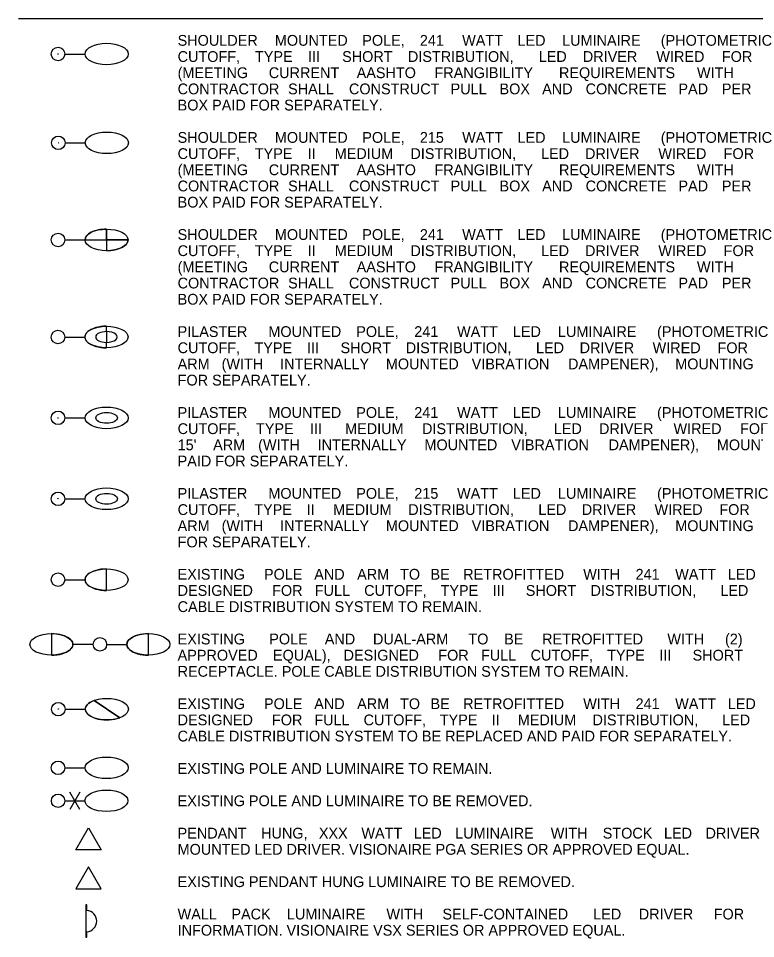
# Model space of a CAD drawing. Extents: x -1452 to -654, y -278 to 245.
# Drawn here: x -1424.2 to -1219, y -15.4 to 240.5 of the extents above; entities that cross this region are included whole.
import ezdxf

# ---------------------------------------------------------------- set-up
doc = ezdxf.new("R2010")
doc.units = 0
for name, color, linetype in [('AdhocPoint_dp', 7, 'Continuous'), ('Logo_dp', 7, 'Continuous'), ('Miscellaneous3', 7, 'Continuous'), ('SheetBorder_dp', 7, 'Continuous'), ('SheetLines_dp', 7, 'Continuous'), ('TextMisc', 7, 'Continuous')]:
    doc.layers.add(name, color=color, linetype=linetype)

# ---------------------------------------------------------------- blocks, each defined once
blk = doc.blocks.new('EPoleLumRmv')
at = {"layer": 'Logo_dp'}
for p, q in [((0, -0.00271), (0, -0.01083)), ((-0.00352, -0.0088), (0.00352, -0.00474)), ((0.00352, -0.0088), (-0.00352, -0.00474))]:
    blk.add_line(p, q, dxfattribs=at)
blk.add_circle((0, 0), 0.00271, dxfattribs=at)
blk.add_ellipse((0, -0.01949), major_axis=(0, -0.00866), ratio=0.5, dxfattribs=at)

msp = doc.modelspace()

# ---------------------------------------------------------------- linework, layer by layer
at = {"layer": 'AdhocPoint_dp'}
for p, q in [((-1405.09, -6.02), (-1405.39, -6.02)), ((-1405.39, -6.02), (-1405.39, -15.02)), ((-1405.09, -7.54), (-1405.09, -6.02)), ((-1405.39, -15.02), (-1405.09, -15.02)), ((-1405.09, -15.02), (-1405.09, -13.51))]:
    msp.add_line(p, q, dxfattribs=at)
for points in [[(-1401.1, 9.31), (-1408.17, 9.31), (-1404.64, 15.43)], [(-1408.17, -1.53), (-1401.1, -1.53), (-1404.64, 4.59)]]:
    msp.add_lwpolyline(points, close=True, dxfattribs=at)
msp.add_arc((-1405.39, -10.52), 3, 275.7392, 84.2608, dxfattribs=at)
at = {"layer": 'Logo_dp'}
msp.add_line((-1411.26, 32.11), (-1405.63, 32.11), dxfattribs=at)
msp.add_circle((-1413.13, 32.11), 1.88, dxfattribs=at)
msp.add_ellipse((-1399.63, 32.11), major_axis=(6, 0), ratio=0.5, dxfattribs=at)
at = {"layer": 'Miscellaneous3'}
msp.add_line((-1424.17, 240.54), (-654.17, 240.54), dxfattribs=at)
at = {"layer": 'SheetLines_dp'}
for p, q in [((-1413.16, 230.6), (-1413.16, 230.67)), ((-1413.16, 230.67), (-1413.09, 230.67)), ((-1413.09, 230.6), (-1413.16, 230.67)), ((-1413.09, 230.6), (-1413.16, 230.6)), ((-1413.09, 230.67), (-1413.09, 230.6)), ((-1413.08, 205.89), (-1413.08, 205.97)), ((-1413.08, 205.97), (-1413.01, 205.97)), ((-1413.01, 205.89), (-1413.08, 205.97)), ((-1413.01, 205.89), (-1413.08, 205.89)), ((-1413.01, 205.97), (-1413.01, 205.89)), ((-1413.16, 129.39), (-1413.16, 129.47)), ((-1413.16, 129.47), (-1413.09, 129.47)), ((-1413.09, 129.39), (-1413.16, 129.47)), ((-1413.09, 129.39), (-1413.16, 129.39)), ((-1413.09, 129.47), (-1413.09, 129.39)), ((-1413.16, 106.89), (-1413.16, 106.97)), ((-1413.16, 106.97), (-1413.09, 106.97)), ((-1413.09, 106.89), (-1413.16, 106.97)), ((-1413.09, 106.89), (-1413.16, 106.89)), ((-1413.09, 106.97), (-1413.09, 106.89)), ((-1413.08, 48.39), (-1413.08, 48.47)), ((-1413.08, 48.47), (-1413.01, 48.47)), ((-1413.01, 48.39), (-1413.08, 48.47)), ((-1413.01, 48.39), (-1413.08, 48.39)), ((-1413.01, 48.47), (-1413.01, 48.39))]:
    msp.add_line(p, q, dxfattribs=at)
at = {"layer": 'TextMisc'}
for p, q in [((-1411.25, 230.63), (-1405.63, 230.63)), ((-1411.17, 205.93), (-1405.55, 205.93)), ((-1399.64, 181.93), (-1399.64, 175.93)), ((-1399.64, 178.93), (-1399.64, 181.93)), ((-1411.25, 178.93), (-1405.63, 178.93)), ((-1405.63, 178.93), (-1393.65, 178.93)), ((-1405.63, 178.93), (-1399.64, 178.93)), ((-1393.65, 178.93), (-1399.64, 178.93)), ((-1399.64, 178.93), (-1399.64, 175.93)), ((-1399.67, 153.43), (-1399.67, 154.93)), ((-1411.29, 151.91), (-1405.66, 151.92)), ((-1399.67, 153.43), (-1399.66, 150.43)), ((-1399.66, 148.93), (-1399.66, 150.43)), ((-1411.25, 129.43), (-1405.63, 129.43)), ((-1411.25, 106.93), (-1405.63, 106.93)), ((-1399.64, 81.43), (-1399.64, 87.43)), ((-1411.25, 84.43), (-1405.63, 84.43)), ((-1414.98, 69.43), (-1414.98, 63.43)), ((-1388.01, 63.43), (-1388.01, 69.43)), ((-1403.37, 66.43), (-1408.99, 66.43)), ((-1399.62, 66.43), (-1394, 66.43)), ((-1403.11, 50.84), (-1395.98, 46.02)), ((-1395.98, 46.02), (-1403.11, 50.84)), ((-1411.17, 48.43), (-1405.55, 48.43))]:
    msp.add_line(p, q, dxfattribs=at)
for centre in [(-1413.13, 230.63), (-1413.05, 205.93), (-1413.13, 178.93), (-1413.16, 151.91), (-1413.13, 129.43), (-1413.13, 106.93), (-1413.13, 84.43), (-1401.49, 66.43), (-1401.49, 66.43), (-1413.05, 48.43)]:
    msp.add_circle(centre, 1.88, dxfattribs=at)
for centre, major_axis in [((-1399.63, 230.63), (6, 0)), ((-1399.55, 205.93), (6, 0)), ((-1399.64, 178.93), (5.99, 0)), ((-1399.66, 151.93), (6, 0.01)), ((-1399.63, 129.43), (6, 0)), ((-1399.63, 129.43), (3, 0)), ((-1399.63, 106.93), (6, 0)), ((-1399.63, 106.93), (3, 0)), ((-1399.63, 106.93), (3, 0)), ((-1399.64, 84.43), (5.99, 0)), ((-1414.98, 66.43), (-5.99, 0)), ((-1388.01, 66.43), (5.99, 0)), ((-1399.55, 48.43), (6, 0))]:
    msp.add_ellipse(centre, major_axis=major_axis, ratio=0.5, dxfattribs=at)
for centre, major_axis, start_param, end_param in [((-1399.64, 178.93), (5.99, 0), 1.570796, 3.141593), ((-1399.64, 178.93), (5.99, 0), 4.712389, 6.283185), ((-1399.66, 151.93), (6, 0.01), 1.570796, 4.712389), ((-1399.66, 151.93), (3, 0), 1.570796, 3.141593), ((-1399.66, 151.93), (3, 0), 3.141593, 4.712389), ((-1399.66, 151.93), (3, 0), 4.712389, 7.853982), ((-1399.64, 84.43), (5.99, 0), 1.570796, 4.712389), ((-1414.98, 66.43), (-5.99, 0), 1.570796, 4.712389), ((-1388.01, 66.43), (5.99, 0), 1.570796, 4.712389), ((-1399.55, 48.43), (6, 0), 2.207405, 5.348998)]:
    msp.add_ellipse(centre, major_axis=major_axis, ratio=0.5, start_param=start_param, end_param=end_param, dxfattribs=at)

# ---------------------------------------------------------------- block references
at = {"layer": 'Logo_dp', "xscale": 690.9505022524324, "yscale": 690.9505022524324, "rotation": 89.99999999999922}
msp.add_blockref('EPoleLumRmv', (-1413.13, 22.94), dxfattribs=at)

# ---------------------------------------------------------------- texts
at = {"layer": 'SheetBorder_dp'}
for s, p in [('SHOULDER ', (-1379.86, 232.93)), ('MOUNTED ', (-1352.8, 232.93)), ('POLE, ', (-1328.47, 232.93)), ('241 ', (-1312.46, 232.93)), ('WATT ', (-1300.68, 232.93)), ('LED ', (-1285.28, 232.93)), ('LUMINAIRE ', (-1272.86, 232.93)), ('(PHOTOMETRIC ', (-1245.41, 232.93)), ('CUTOFF, ', (-1379.86, 228.43)), ('TYPE ', (-1358.33, 228.43)), ('III ', (-1343.56, 228.43)), ('SHORT ', (-1334.09, 228.43)), ('DISTRIBUTION, ', (-1315.78, 228.43)), ('LED ', (-1279.39, 228.43)), ('DRIVER ', (-1267.1, 228.43)), ('WIRED ', (-1246.64, 228.43)), ('FOR ', (-1228.41, 228.43)), ('(MEETING ', (-1379.86, 223.93)), ('CURRENT ', (-1354.5, 223.93)), ('AASHTO ', (-1330.04, 223.93)), ('FRANGIBILITY ', (-1308.39, 223.93)), ('REQUIREMENTS ', (-1273.74, 223.93)), ('WITH ', (-1235.34, 223.93)), ('CONTRACTOR ', (-1379.86, 219.43)), ('SHALL ', (-1349.13, 219.43)), ('CONSTRUCT ', (-1332.18, 219.43)), ('PULL ', (-1303.9, 219.43)), ('BOX ', (-1290.29, 219.43)), ('AND ', (-1278.42, 219.43)), ('CONCRETE ', (-1266.32, 219.43)), ('PAD ', (-1240.5, 219.43)), ('PER ', (-1228.42, 219.43)), ('BOX PAID FOR SEPARATELY.', (-1379.86, 214.93)), ('SHOULDER ', (-1379.86, 205.93)), ('MOUNTED ', (-1352.8, 205.93)), ('POLE, ', (-1328.47, 205.93)), ('215 ', (-1312.46, 205.93)), ('WATT ', (-1300.68, 205.93)), ('LED ', (-1285.28, 205.93)), ('LUMINAIRE ', (-1272.86, 205.93)), ('(PHOTOMETRIC ', (-1245.41, 205.93)), ('CUTOFF, ', (-1379.86, 201.43)), ('TYPE ', (-1358.39, 201.43)), ('II ', (-1343.67, 201.43)), ('MEDIUM ', (-1336.14, 201.43)), ('DISTRIBUTION, ', (-1315.08, 201.43)), ('LED ', (-1278.74, 201.43)), ('DRIVER ', (-1266.5, 201.43)), ('WIRED ', (-1246.09, 201.43)), ('FOR ', (-1227.92, 201.43)), ('(MEETING ', (-1379.86, 196.93)), ('CURRENT ', (-1354.5, 196.93)), ('AASHTO ', (-1330.04, 196.93)), ('FRANGIBILITY ', (-1308.39, 196.93)), ('REQUIREMENTS ', (-1273.74, 196.93)), ('WITH ', (-1235.34, 196.93)), ('CONTRACTOR ', (-1379.86, 192.43)), ('SHALL ', (-1349.13, 192.43)), ('CONSTRUCT ', (-1332.18, 192.43)), ('PULL ', (-1303.9, 192.43)), ('BOX ', (-1290.29, 192.43)), ('AND ', (-1278.42, 192.43)), ('CONCRETE ', (-1266.32, 192.43)), ('PAD ', (-1240.5, 192.43)), ('PER ', (-1228.42, 192.43)), ('BOX PAID FOR SEPARATELY.', (-1379.86, 187.93)), ('SHOULDER ', (-1379.86, 178.93)), ('MOUNTED ', (-1352.8, 178.93)), ('POLE, ', (-1328.47, 178.93)), ('241 ', (-1312.46, 178.93)), ('WATT ', (-1300.68, 178.93)), ('LED ', (-1285.28, 178.93)), ('LUMINAIRE ', (-1272.86, 178.93)), ('(PHOTOMETRIC ', (-1245.41, 178.93)), ('CUTOFF, ', (-1379.86, 174.43)), ('TYPE ', (-1358.39, 174.43)), ('II ', (-1343.67, 174.43)), ('MEDIUM ', (-1336.14, 174.43)), ('DISTRIBUTION, ', (-1315.08, 174.43)), ('LED ', (-1278.74, 174.43)), ('DRIVER ', (-1266.5, 174.43)), ('WIRED ', (-1246.09, 174.43)), ('FOR ', (-1227.92, 174.43)), ('(MEETING ', (-1379.86, 169.93)), ('CURRENT ', (-1354.5, 169.93)), ('AASHTO ', (-1330.04, 169.93)), ('FRANGIBILITY ', (-1308.39, 169.93)), ('REQUIREMENTS ', (-1273.74, 169.93)), ('WITH ', (-1235.34, 169.93)), ('CONTRACTOR ', (-1379.86, 165.43)), ('SHALL ', (-1349.13, 165.43)), ('CONSTRUCT ', (-1332.18, 165.43)), ('PULL ', (-1303.9, 165.43)), ('BOX ', (-1290.29, 165.43)), ('AND ', (-1278.42, 165.43)), ('CONCRETE ', (-1266.32, 165.43)), ('PAD ', (-1240.5, 165.43)), ('PER ', (-1228.42, 165.43)), ('BOX PAID FOR SEPARATELY.', (-1379.86, 160.93)), ('PILASTER ', (-1379.86, 151.93)), ('MOUNTED ', (-1354.61, 151.93)), ('POLE, ', (-1330.15, 151.93)), ('241 ', (-1314.01, 151.93)), ('WATT ', (-1302.1, 151.93)), ('LED ', (-1286.57, 151.93)), ('LUMINAIRE ', (-1274.03, 151.93)), ('(PHOTOMETRIC ', (-1246.45, 151.93)), ('CUTOFF, ', (-1379.86, 147.43)), ('TYPE ', (-1358.48, 147.43)), ('III ', (-1343.86, 147.43)), ('SHORT ', (-1334.53, 147.43)), ('DISTRIBUTION, ', (-1316.38, 147.43)), ('LED ', (-1280.14, 147.43)), ('DRIVER ', (-1267.99, 147.43)), ('WIRED ', (-1247.68, 147.43)), ('FOR ', (-1229.61, 147.43)), ('ARM ', (-1379.86, 142.93)), ('(WITH ', (-1367.62, 142.93)), ('INTERNALLY ', (-1351.34, 142.93)), ('MOUNTED ', (-1321.91, 142.93)), ('VIBRATION ', (-1298.03, 142.93)), ('DAMPENER), ', (-1271.22, 142.93)), ('MOUNTING ', (-1241.38, 142.93)), ('FOR SEPARATELY.', (-1379.86, 138.43)), ('PILASTER ', (-1379.86, 129.43)), ('MOUNTED ', (-1354.61, 129.43)), ('POLE, ', (-1330.15, 129.43)), ('241 ', (-1314.01, 129.43)), ('WATT ', (-1302.1, 129.43)), ('LED ', (-1286.57, 129.43)), ('LUMINAIRE ', (-1274.03, 129.43)), ('(PHOTOMETRIC ', (-1246.45, 129.43)), ('CUTOFF, ', (-1379.86, 124.93)), ('DISTRIBUTION, ', (-1311.85, 124.93)), ('FOR ', (-1223.36, 124.93)), ('TYPE ', (-1358.05, 124.93)), ('III ', (-1343, 124.93)), ('MEDIUM ', (-1333.25, 124.93)), ('LED ', (-1275.18, 124.93)), ('DRIVER ', (-1262.6, 124.93)), ('WIRED ', (-1241.86, 124.93)), ("15' ", (-1379.86, 120.43)), ('ARM ', (-1369.98, 120.43)), ('(WITH ', (-1357.45, 120.43)), ('INTERNALLY ', (-1340.9, 120.43)), ('MOUNTED ', (-1311.18, 120.43)), ('VIBRATION ', (-1287.02, 120.43)), ('DAMPENER), ', (-1259.93, 120.43)), ('MOUNTING ', (-1229.81, 120.43)), ('PAID FOR SEPARATELY.', (-1379.86, 115.93)), ('(PHOTOMETRIC ', (-1246.45, 106.93)), ('PILASTER ', (-1379.86, 106.93)), ('MOUNTED ', (-1354.61, 106.93)), ('POLE, ', (-1330.15, 106.93)), ('215 ', (-1314.01, 106.93)), ('WATT ', (-1302.1, 106.93)), ('LED ', (-1286.57, 106.93)), ('LUMINAIRE ', (-1274.03, 106.93)), ('CUTOFF, ', (-1379.86, 102.43)), ('TYPE ', (-1358.54, 102.43)), ('II ', (-1343.97, 102.43)), ('MEDIUM ', (-1336.59, 102.43)), ('DISTRIBUTION, ', (-1315.68, 102.43)), ('LED ', (-1279.49, 102.43)), ('DRIVER ', (-1267.4, 102.43)), ('WIRED ', (-1247.14, 102.43)), ('FOR ', (-1229.12, 102.43)), ('ARM ', (-1379.86, 97.93)), ('(WITH ', (-1367.62, 97.93)), ('INTERNALLY ', (-1351.34, 97.93)), ('MOUNTED ', (-1321.91, 97.93)), ('VIBRATION ', (-1298.03, 97.93)), ('DAMPENER), ', (-1271.22, 97.93)), ('MOUNTING ', (-1241.38, 97.93)), ('FOR SEPARATELY.', (-1379.86, 93.43)), ('EXISTING ', (-1379.86, 84.43)), ('POLE ', (-1355.83, 84.43)), ('AND ', (-1341.85, 84.43)), ('ARM ', (-1329.91, 84.43)), ('TO ', (-1317.97, 84.43)), ('BE ', (-1309.48, 84.43)), ('RETROFITTED ', (-1300.39, 84.43)), ('WITH ', (-1267, 84.43)), ('241 ', (-1252.43, 84.43)), ('WATT ', (-1241.4, 84.43)), ('LED ', (-1226.76, 84.43)), ('DESIGNED ', (-1379.86, 79.93)), ('FOR ', (-1353.56, 79.93)), ('FULL ', (-1341.7, 79.93)), ('CUTOFF, ', (-1327.95, 79.93)), ('TYPE ', (-1306.69, 79.93)), ('III ', (-1292.19, 79.93)), ('SHORT ', (-1282.99, 79.93)), ('DISTRIBUTION, ', (-1264.96, 79.93)), ('LED ', (-1228.84, 79.93)), ('CABLE DISTRIBUTION SYSTEM TO REMAIN.', (-1379.86, 75.43)), ('EXISTING ', (-1379.86, 66.43)), ('POLE ', (-1354.36, 66.43)), ('AND ', (-1338.91, 66.43)), ('DUAL-ARM ', (-1325.5, 66.43)), ('TO ', (-1298.95, 66.43)), ('BE ', (-1289, 66.43)), ('RETROFITTED ', (-1278.43, 66.43)), ('WITH ', (-1243.58, 66.43)), ('(2) ', (-1227.54, 66.43)), ('APPROVED ', (-1379.86, 61.93)), ('EQUAL), ', (-1353.33, 61.93)), ('DESIGNED ', (-1333.67, 61.93)), ('FOR ', (-1307.33, 61.93)), ('FULL ', (-1295.43, 61.93)), ('CUTOFF, ', (-1281.63, 61.93)), ('TYPE ', (-1260.34, 61.93)), ('III ', (-1245.8, 61.93)), ('SHORT ', (-1236.56, 61.93)), ('RECEPTACLE. POLE CABLE DISTRIBUTION SYSTEM TO REMAIN.', (-1379.86, 57.43)), ('EXISTING ', (-1379.86, 48.43)), ('POLE ', (-1355.83, 48.43)), ('AND ', (-1341.85, 48.43)), ('ARM ', (-1329.91, 48.43)), ('TO ', (-1317.97, 48.43)), ('BE ', (-1309.48, 48.43)), ('RETROFITTED ', (-1300.39, 48.43)), ('WITH ', (-1267, 48.43)), ('241 ', (-1252.43, 48.43)), ('WATT ', (-1241.4, 48.43)), ('LED ', (-1226.76, 48.43)), ('DESIGNED ', (-1379.86, 43.93)), ('FOR ', (-1353.61, 43.93)), ('FULL ', (-1341.81, 43.93)), ('CUTOFF, ', (-1328.11, 43.93)), ('TYPE ', (-1306.91, 43.93)), ('II ', (-1292.46, 43.93)), ('MEDIUM ', (-1285.2, 43.93)), ('DISTRIBUTION, ', (-1264.41, 43.93)), ('LED ', (-1228.35, 43.93)), ('CABLE DISTRIBUTION SYSTEM TO BE REPLACED AND PAID FOR SEPARATELY. ', (-1379.86, 39.43)), ('EXISTING POLE AND LUMINAIRE TO REMAIN.', (-1379.86, 30.43)), ('EXISTING POLE AND LUMINAIRE TO BE REMOVED.', (-1379.86, 21.43)), ('PENDANT ', (-1379.86, 12.43)), ('HUNG, ', (-1356.63, 12.43)), ('XXX ', (-1340.56, 12.43)), ('WATT ', (-1328.72, 12.43)), ('LED ', (-1314.18, 12.43)), ('LUMINAIRE ', (-1302.62, 12.43)), ('WITH ', (-1276.03, 12.43)), ('STOCK ', (-1261.57, 12.43)), ('LED ', (-1244.52, 12.43)), ('DRIVER ', (-1232.96, 12.43)), ('MOUNTED LED DRIVER. VISIONAIRE PGA SERIES OR APPROVED EQUAL.', (-1379.86, 7.93)), ('EXISTING PENDANT HUNG LUMINAIRE TO BE REMOVED.', (-1379.86, -1.07)), ('WALL ', (-1379.86, -10.07)), ('PACK ', (-1364.89, -10.07)), ('LUMINAIRE ', (-1349.45, -10.07)), ('WITH ', (-1321.75, -10.07)), ('SELF-CONTAINED ', (-1306.17, -10.07)), ('LED ', (-1264.21, -10.07)), ('DRIVER ', (-1251.53, -10.07)), ('FOR ', (-1230.69, -10.07)), ('INFORMATION. VISIONAIRE VSX SERIES OR APPROVED EQUAL.', (-1379.86, -14.57))]:
    msp.add_text(s, height=3, dxfattribs=at).set_placement(p)

doc.saveas('drawing.dxf')
